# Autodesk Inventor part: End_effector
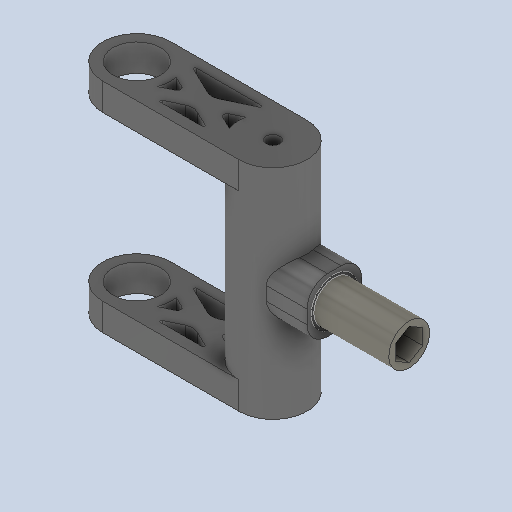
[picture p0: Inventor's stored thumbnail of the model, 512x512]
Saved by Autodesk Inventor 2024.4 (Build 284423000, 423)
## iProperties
Created: 2025-07
Part Number: End_effector
Material: Generic
Document SubType Name: Modeling
Designer: AdminForWorker
Density: 1 g/cm^3
Appearance: Default
Title: End_effector v2
Author: AdminForWorker
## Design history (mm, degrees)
feature "Body10"
feature "Body11"
body "Solid1"
body "Solid2"
